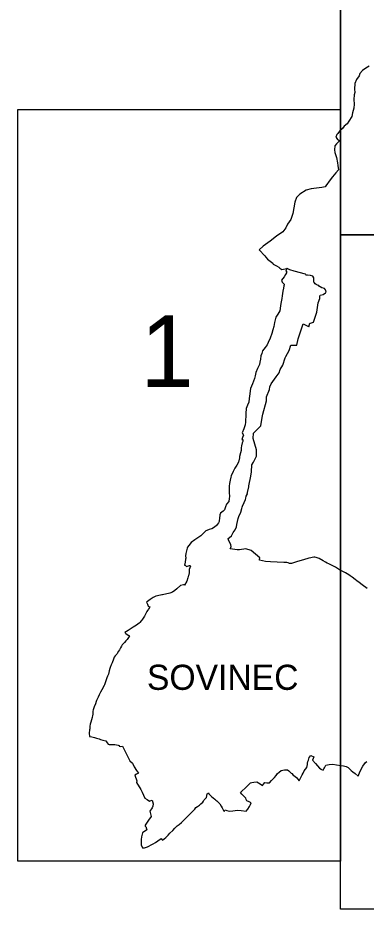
# Model space of a CAD drawing. Extents: x -547343 to -529607, y -1096298 to -1087453.
# Drawn here: x -532851 to -532756.9, y -1089566.1 to -1089325.1 of the extents above; entities that cross this region are included whole.
import ezdxf

# ---------------------------------------------------------------- set-up
doc = ezdxf.new("R2010")
doc.units = 0
doc.layers.add('Vrstva 18', color=7, linetype='Continuous')
doc.layers.add('Vrstva 9', color=7, linetype='Continuous')

msp = doc.modelspace()

# ---------------------------------------------------------------- linework, layer by layer
at = {"layer": 'Vrstva 18'}
for points in [[(-532676.65, -1089201.45), (-532763.82, -1089201.45), (-532763.82, -1089383.77), (-532676.65, -1089383.77)], [(-532763.82, -1089349.85), (-532763.82, -1089553.12), (-532850.99, -1089553.12), (-532850.99, -1089349.85)], [(-532676.65, -1089383.77), (-532676.65, -1089566.09), (-532763.82, -1089566.09), (-532763.82, -1089383.77)]]:
    msp.add_lwpolyline(points, close=True, dxfattribs=at)
for points in [[(-532756.12, -1089338.18), (-532757.02, -1089338.71), (-532757.91, -1089339.3), (-532758.64, -1089340.17), (-532758.79, -1089340.77), (-532759.5, -1089341.77), (-532759.95, -1089342.86), (-532760.04, -1089344.39), (-532759.97, -1089345.3), (-532760.18, -1089345.94), (-532760.26, -1089347.13), (-532760.16, -1089348.44), (-532760.26, -1089349.48), (-532760.58, -1089350.74), (-532760.83, -1089351.78), (-532761.57, -1089353.07), (-532762.06, -1089353.75), (-532762.86, -1089354.41), (-532763.34, -1089354.98), (-532764.01, -1089355.64), (-532764.41, -1089356.05), (-532764.57, -1089356.36), (-532764.85, -1089356.64), (-532765.1, -1089357.37), (-532764.76, -1089357.79), (-532764.12, -1089358.34), (-532764.56, -1089358.77), (-532764.96, -1089359.14), (-532765.36, -1089359.71), (-532765.44, -1089360.77), (-532765.37, -1089361.53), (-532764.92, -1089362.84), (-532764.68, -1089364.27), (-532764.6, -1089365.03), (-532764.37, -1089366.16), (-532765.12, -1089367), (-532766.04, -1089368.08), (-532766.66, -1089368.85), (-532767.86, -1089370.47), (-532768.04, -1089370.75), (-532768.93, -1089370.96), (-532771.75, -1089371.31), (-532773.16, -1089371.65), (-532774.83, -1089372.73), (-532775.76, -1089373.71), (-532776.21, -1089374.93), (-532776.74, -1089378.01), (-532777.24, -1089379.58), (-532778.15, -1089380.84), (-532778.6, -1089381.86), (-532779.45, -1089382.91), (-532781.16, -1089384.15), (-532782.81, -1089385.48), (-532784.76, -1089386.81), (-532785.82, -1089387.78), (-532784.31, -1089389.41), (-532784, -1089389.83), (-532783.56, -1089390.3), (-532782.13, -1089391.39), (-532782.02, -1089391.73), (-532781.13, -1089392.11), (-532780.53, -1089392.5), (-532780.2, -1089392.75), (-532779.69, -1089393.1), (-532778.38, -1089392.82), (-532778.63, -1089393.55), (-532778.45, -1089393.59), (-532778.48, -1089394.07), (-532778.67, -1089394.49), (-532779.07, -1089395.09), (-532779.76, -1089396.06), (-532779.58, -1089396.55), (-532779.04, -1089397.13), (-532779.08, -1089397.32), (-532779.13, -1089397.55), (-532779.26, -1089398.18), (-532779.39, -1089398.95), (-532779.61, -1089400.23), (-532779.74, -1089400.95), (-532779.92, -1089401.87), (-532780.06, -1089402.86), (-532780.17, -1089403.71), (-532780.26, -1089404.32), (-532780.8, -1089405.17), (-532781.32, -1089406.04), (-532781.64, -1089407.43), (-532781.89, -1089408.55), (-532782.13, -1089409.49), (-532782.36, -1089410.4), (-532782.88, -1089411.66), (-532783.39, -1089412.9), (-532783.67, -1089413.53), (-532784.22, -1089414.24), (-532784.93, -1089415.12), (-532785.14, -1089415.84), (-532785.33, -1089416.46), (-532785.5, -1089417.35), (-532785.65, -1089418.15), (-532785.77, -1089418.85), (-532786.25, -1089419.91), (-532786.76, -1089421.02), (-532786.92, -1089421.87), (-532787.07, -1089422.63), (-532787.61, -1089424.01), (-532788.14, -1089425.31), (-532788.41, -1089427.36), (-532788.52, -1089428.05), (-532788.65, -1089429.03), (-532788.99, -1089429.82), (-532789.37, -1089430.73), (-532789.43, -1089432.05), (-532789.46, -1089432.98), (-532789.49, -1089433.73), (-532789.55, -1089434.43), (-532789.63, -1089435.13), (-532789.99, -1089436.2), (-532790.37, -1089437.29), (-532790.05, -1089437.92), (-532790.28, -1089438.54), (-532790.5, -1089439.07), (-532790.21, -1089439.11), (-532790.24, -1089439.65), (-532790.37, -1089440.04), (-532790.63, -1089440.82), (-532790.65, -1089441.34), (-532790.67, -1089442.05), (-532790.84, -1089442.72), (-532791.09, -1089443.65), (-532791.17, -1089444.03), (-532791.4, -1089445.26), (-532791.88, -1089446.01), (-532792.39, -1089446.85), (-532792.84, -1089447.76), (-532793.39, -1089448.9), (-532793.47, -1089449.25), (-532793.68, -1089450.07), (-532793.84, -1089450.99), (-532793.89, -1089451.74), (-532793.95, -1089452.65), (-532793.9, -1089453.4), (-532793.82, -1089454.54), (-532793.89, -1089455.08), (-532794, -1089455.87), (-532794.64, -1089456.59), (-532794.87, -1089457.29), (-532795.06, -1089457.82), (-532795.21, -1089458.14), (-532795.55, -1089458.45), (-532796.29, -1089459.06), (-532796.44, -1089459.51), (-532796.46, -1089459.72), (-532796.49, -1089460.2), (-532796.65, -1089461.25), (-532796.84, -1089461.63), (-532797.08, -1089461.98), (-532797.38, -1089462.34), (-532797.92, -1089462.77), (-532798.57, -1089463.27), (-532799.28, -1089463.43), (-532799.96, -1089463.69), (-532800.18, -1089463.82), (-532800.84, -1089464.41), (-532801.6, -1089465.14), (-532802.36, -1089465.69), (-532803.21, -1089466.26), (-532804.16, -1089466.92), (-532804.81, -1089467.74), (-532805.15, -1089468.2), (-532805.27, -1089468.47), (-532805.64, -1089469.88), (-532805.69, -1089470.54), (-532805.62, -1089471.16), (-532805.67, -1089471.49), (-532805.83, -1089472.29), (-532805.94, -1089473.05), (-532805.83, -1089473.12), (-532805.54, -1089473.33), (-532805.54, -1089473.33), (-532805.52, -1089473.35), (-532805.44, -1089473.4), (-532804.66, -1089473.13), (-532804.57, -1089473.18), (-532804.45, -1089473.26), (-532804.39, -1089473.31), (-532804.36, -1089473.32), (-532804.68, -1089474.22), (-532804.74, -1089474.98), (-532804.76, -1089475.18), (-532804.94, -1089475.96), (-532804.98, -1089476.11), (-532805.08, -1089476.54), (-532805.39, -1089477.41), (-532806, -1089478.44), (-532806.09, -1089478.39), (-532806.21, -1089478.38), (-532807.02, -1089478.55), (-532807.95, -1089479.36), (-532808.05, -1089479.45), (-532808.63, -1089479.93), (-532809.2, -1089480.34), (-532809.9, -1089480.62), (-532811.93, -1089481.06), (-532812.14, -1089481.11), (-532812.42, -1089481.18), (-532813.68, -1089481.49), (-532814.05, -1089481.66), (-532814.41, -1089481.81), (-532814.68, -1089481.99), (-532815.26, -1089482.39), (-532815.58, -1089482.59), (-532815.99, -1089482.93), (-532816.21, -1089483.12), (-532816.01, -1089483.63), (-532815.75, -1089484.16), (-532815.35, -1089484.3), (-532815.44, -1089484.48), (-532815.62, -1089484.75), (-532815.74, -1089484.93), (-532815.98, -1089485.3), (-532816.11, -1089485.56), (-532816.39, -1089486.11), (-532816.58, -1089486.53), (-532816.81, -1089486.87), (-532817.13, -1089487.38), (-532817.49, -1089487.95), (-532817.66, -1089488.14), (-532818.05, -1089488.6), (-532818.25, -1089488.78), (-532818.56, -1089489), (-532818.97, -1089489.28), (-532819.37, -1089489.53), (-532819.83, -1089489.84), (-532820.42, -1089490.23), (-532821.22, -1089490.72), (-532822.09, -1089491.26), (-532822.01, -1089491.34), (-532821.81, -1089491.53), (-532821.23, -1089492.01), (-532820.81, -1089492.22), (-532821.09, -1089492.66), (-532821.44, -1089493.2), (-532821.8, -1089493.57), (-532822.21, -1089493.98), (-532822.57, -1089494.34), (-532822.78, -1089494.65), (-532823, -1089494.96), (-532823.25, -1089495.44), (-532823.54, -1089495.97), (-532823.76, -1089496.35), (-532824.16, -1089496.96), (-532824.29, -1089497.12), (-532824.69, -1089497.62), (-532824.95, -1089497.96), (-532825.17, -1089498.53), (-532825.55, -1089499.48), (-532825.79, -1089500.06), (-532826.09, -1089500.75), (-532826.16, -1089501.02), (-532826.33, -1089501.69), (-532826.55, -1089502.59), (-532826.62, -1089502.74), (-532826.75, -1089503.08), (-532826.92, -1089503.5), (-532827.14, -1089504.09), (-532827.4, -1089504.85), (-532827.6, -1089505.41), (-532827.71, -1089505.64), (-532828.3, -1089506.78), (-532828.64, -1089507.4), (-532828.86, -1089507.73), (-532829.04, -1089508.14), (-532829.31, -1089508.73), (-532829.72, -1089509.64), (-532829.83, -1089509.96), (-532830.06, -1089510.57), (-532830.34, -1089511.35), (-532830.64, -1089512.16), (-532830.7, -1089512.55), (-532830.73, -1089512.84), (-532830.78, -1089513.5), (-532830.82, -1089513.72), (-532830.96, -1089514.25), (-532831.3, -1089515.49), (-532831.48, -1089516.1), (-532831.52, -1089516.64), (-532831.58, -1089517.31), (-532831.61, -1089517.58), (-532831.69, -1089518.47), (-532831.6, -1089519.37), (-532830.97, -1089519.5), (-532830.3, -1089519.65), (-532829.75, -1089519.83), (-532829.04, -1089520.05), (-532828.64, -1089520.18), (-532828.05, -1089520.36), (-532827.21, -1089520.61), (-532827.06, -1089520.82), (-532826.83, -1089521.13), (-532826.58, -1089521.49), (-532826.37, -1089521.52), (-532825.78, -1089521.58), (-532824.83, -1089521.57), (-532823.88, -1089521.77), (-532823.65, -1089521.87), (-532823.59, -1089522.02), (-532823.38, -1089522.08), (-532822.7, -1089521.98), (-532821.22, -1089525.11), (-532820.71, -1089525.98), (-532820.03, -1089526.58), (-532819.54, -1089527.56), (-532818.97, -1089528.6), (-532818.37, -1089529.29), (-532818.74, -1089529.52), (-532818.92, -1089529.62), (-532819.38, -1089529.9), (-532818.84, -1089531.39), (-532818.98, -1089531.85), (-532817.77, -1089533.7), (-532817.44, -1089534.45), (-532816.68, -1089536.06), (-532816.07, -1089536.42), (-532815.4, -1089536.88), (-532815.23, -1089536.84), (-532814.68, -1089536.58), (-532814.43, -1089537.63), (-532814.55, -1089538.27), (-532814.68, -1089538.65), (-532815.37, -1089539.63), (-532815.02, -1089541.01), (-532815.67, -1089542.05), (-532816.64, -1089543.34), (-532816.62, -1089543.62), (-532816.37, -1089543.94), (-532816.29, -1089544.07), (-532816.22, -1089544.41), (-532816.18, -1089544.64), (-532817.28, -1089545.41), (-532817.57, -1089546.56), (-532817.65, -1089547.25), (-532817.68, -1089547.48), (-532817.68, -1089548.69), (-532817.28, -1089549.54), (-532816.82, -1089549.51), (-532815.96, -1089549.21), (-532814.6, -1089548.51), (-532814.46, -1089548.43), (-532813.78, -1089548.02), (-532813.21, -1089547.63), (-532812.28, -1089547), (-532812.06, -1089547.25), (-532811.92, -1089547.4), (-532811.06, -1089546.73), (-532810.41, -1089546.07), (-532809.91, -1089545.56), (-532809.15, -1089544.79), (-532808.58, -1089544.23), (-532807.92, -1089543.58), (-532807.42, -1089543.16), (-532806.82, -1089542.61), (-532806.38, -1089542.23), (-532805.85, -1089541.74), (-532805.4, -1089541.3), (-532804.78, -1089540.69), (-532804.23, -1089540.16), (-532803.6, -1089539.52), (-532803.21, -1089539.02), (-532802.88, -1089538.58), (-532802.46, -1089538.29), (-532801.97, -1089537.94), (-532801.56, -1089537.58), (-532801.07, -1089537.15), (-532800.89, -1089536.88), (-532800.71, -1089536.55), (-532800.51, -1089536.38), (-532800.33, -1089536.2), (-532800.02, -1089535.89), (-532799.85, -1089534.94), (-532799.64, -1089534.78), (-532799.46, -1089534.62), (-532799.41, -1089534.93), (-532799.07, -1089535.23), (-532798.92, -1089535.37), (-532798.58, -1089535.68), (-532798.23, -1089535.98), (-532797.83, -1089536.31), (-532797.51, -1089536.59), (-532797.21, -1089536.84), (-532796.87, -1089537.14), (-532796.41, -1089537.57), (-532796.07, -1089538.2), (-532795.79, -1089538.73), (-532795.45, -1089539.4), (-532795.15, -1089539.57), (-532795.01, -1089539.27), (-532794.52, -1089539.43), (-532793.96, -1089539.62), (-532792.9, -1089539.47), (-532791.71, -1089539.31), (-532790.72, -1089539.41), (-532789.32, -1089539.56), (-532788.92, -1089539.02), (-532788.43, -1089538.37), (-532788.16, -1089537.82), (-532787.94, -1089537.36), (-532788.49, -1089537.11), (-532789.15, -1089536.8), (-532789.29, -1089536.43), (-532789.4, -1089536.09), (-532789.73, -1089535.77), (-532790.48, -1089535), (-532790.89, -1089534.58), (-532790.37, -1089534.07), (-532789.62, -1089533.35), (-532789.04, -1089532.8), (-532788.14, -1089531.94), (-532787.79, -1089531.86), (-532787.23, -1089531.77), (-532786.44, -1089531.64), (-532785.58, -1089532.24), (-532784.96, -1089532.65), (-532784.63, -1089532.25), (-532784.26, -1089531.83), (-532783.74, -1089531.89), (-532783.01, -1089531.94), (-532782.45, -1089531.29), (-532781.98, -1089530.76), (-532781.67, -1089530.51), (-532781.26, -1089529.99), (-532780.84, -1089529.45), (-532780.39, -1089529.01), (-532779.92, -1089528.57), (-532779.39, -1089528.48), (-532778.97, -1089528.4), (-532778.66, -1089528.37), (-532778.19, -1089528.42), (-532777.85, -1089528.72), (-532777.47, -1089529.05), (-532777.27, -1089529.24), (-532777.16, -1089529.32), (-532776.99, -1089529.4), (-532776.61, -1089529.86), (-532776.2, -1089530.16), (-532775.63, -1089530.57), (-532775.34, -1089530.93), (-532774.99, -1089531.35), (-532774.63, -1089530.63), (-532774.21, -1089529.8), (-532773.94, -1089529.3), (-532773.63, -1089528.71), (-532773.28, -1089528.23), (-532772.93, -1089527.75), (-532772.8, -1089526.98), (-532772.74, -1089526.64), (-532772.64, -1089526.18), (-532772.52, -1089525.76), (-532772.32, -1089525.09), (-532771.88, -1089524.5), (-532771.07, -1089524.9), (-532771.38, -1089525.76), (-532770.64, -1089526.71), (-532770.07, -1089527.31), (-532769.49, -1089527.94), (-532769.1, -1089528.25), (-532768.99, -1089528.31), (-532768.5, -1089528.51), (-532768.35, -1089528.1), (-532768.21, -1089527.84), (-532767.79, -1089527.13), (-532766.87, -1089527), (-532765.94, -1089526.89), (-532764.89, -1089527.07), (-532763.76, -1089527.25), (-532763.05, -1089527.37), (-532762.32, -1089527.48), (-532761.79, -1089527.82), (-532761.51, -1089528.02), (-532761.28, -1089528.28), (-532761.01, -1089528.59), (-532760.5, -1089528.99), (-532759.91, -1089529.44), (-532759.06, -1089530.1), (-532758.68, -1089529.22), (-532758.39, -1089528.44), (-532757.8, -1089527.46), (-532757.13, -1089526.44), (-532756.76, -1089526.14)], [(-532769.45, -1089400.68), (-532769.41, -1089400.22), (-532769.39, -1089400.03), (-532768.54, -1089399.92), (-532767.95, -1089399.46), (-532767.78, -1089399.27), (-532767.71, -1089399.21), (-532767.95, -1089398.63), (-532768.22, -1089398.29), (-532768.5, -1089398.2), (-532768.86, -1089398.06), (-532769.31, -1089397.85), (-532769.5, -1089397.69), (-532769.73, -1089397.47), (-532770.06, -1089397.34), (-532770.42, -1089397.16), (-532770.73, -1089396.97), (-532770.91, -1089396.74), (-532771.04, -1089396.54), (-532771.1, -1089396.46), (-532771.1, -1089396.24), (-532771.1, -1089396.09), (-532771.08, -1089395.73), (-532771.06, -1089395.35), (-532771.31, -1089394.93), (-532771.99, -1089394.8), (-532772.76, -1089394.67), (-532773.16, -1089394.63), (-532773.18, -1089394.58), (-532773.32, -1089394.44), (-532776.36, -1089393.54), (-532777.55, -1089393.18), (-532778.06, -1089392.96), (-532778.22, -1089392.89), (-532778.38, -1089392.82)], [(-532756.69, -1089479.42), (-532758.04, -1089478.41), (-532758.77, -1089477.72), (-532759.45, -1089477.27), (-532759.92, -1089476.91), (-532760.69, -1089476.29), (-532761.21, -1089475.92), (-532761.62, -1089475.65), (-532762.02, -1089475.45), (-532762.53, -1089475.18), (-532763.78, -1089474.55), (-532764.15, -1089474.32), (-532765.24, -1089473.65), (-532765.72, -1089473.35), (-532765.96, -1089473.23), (-532766.45, -1089473), (-532767.04, -1089472.73), (-532767.42, -1089472.54), (-532767.87, -1089472.29), (-532768.58, -1089471.88), (-532769.65, -1089471.28), (-532770.45, -1089471.01), (-532770.82, -1089470.89), (-532770.95, -1089470.87), (-532771.09, -1089470.89), (-532771.47, -1089470.96), (-532771.9, -1089471.05), (-532772.41, -1089471.19), (-532773.89, -1089471.64), (-532775.49, -1089472.12), (-532776.25, -1089472.35), (-532777.1, -1089472.63), (-532777.64, -1089472.59), (-532777.97, -1089472.49), (-532778.38, -1089472.35), (-532779.16, -1089472.32), (-532780.97, -1089472.24), (-532782.79, -1089472.16), (-532784.15, -1089472.1), (-532785.71, -1089471.74), (-532785.7, -1089471.68), (-532785.69, -1089471.53), (-532785.66, -1089471.12), (-532787.94, -1089469.07), (-532789.41, -1089468.69), (-532791.16, -1089468.9), (-532791.78, -1089468.97), (-532793.66, -1089468.66), (-532793.58, -1089468.45), (-532793.5, -1089468.27), (-532793.4, -1089468.06), (-532793.5, -1089467.57), (-532794.08, -1089466.19), (-532794.22, -1089466), (-532794.26, -1089465.94), (-532793.27, -1089465.1), (-532793.02, -1089464.59), (-532792.86, -1089464.23), (-532792.29, -1089463.5), (-532791.95, -1089462.73), (-532791.82, -1089462.05), (-532791.48, -1089460.44), (-532791.28, -1089459.96), (-532790.79, -1089458.78), (-532790.46, -1089457.77), (-532790.38, -1089457.36), (-532790.3, -1089457.09), (-532789.88, -1089456.11), (-532789.52, -1089455.31), (-532789.43, -1089454.98), (-532789.29, -1089454.38), (-532789.05, -1089454.01), (-532788.98, -1089453.77), (-532789.03, -1089453.76), (-532788.99, -1089453.55), (-532788.97, -1089453.45), (-532788.65, -1089451.86), (-532788.61, -1089451.61), (-532788.1, -1089448.99), (-532787.89, -1089447.83), (-532787.79, -1089445.92), (-532787.38, -1089445.19), (-532786.5, -1089443.59), (-532786.5, -1089441.85), (-532787.43, -1089438.82), (-532787.31, -1089437.39), (-532785.35, -1089435.43), (-532785.02, -1089433.17), (-532784.87, -1089432.22), (-532783.87, -1089428.64), (-532783.82, -1089427.53), (-532783, -1089425.61), (-532782.91, -1089424.9), (-532782.6, -1089424.04), (-532781.22, -1089422.18), (-532780.38, -1089421.05), (-532780.15, -1089420.18), (-532779.45, -1089419), (-532778.83, -1089417.03), (-532778.61, -1089416.68), (-532777.75, -1089415.06), (-532777.23, -1089413.56), (-532777.11, -1089413.57), (-532775.69, -1089413.56), (-532775.25, -1089411.91), (-532773.97, -1089407.82), (-532772.54, -1089408.59), (-532772.43, -1089408.65), (-532772.15, -1089407.67), (-532771.95, -1089407.6), (-532771.14, -1089407.33), (-532770.26, -1089404.66), (-532769.85, -1089402.12), (-532769.47, -1089400.95), (-532769.45, -1089400.68)]]:
    msp.add_lwpolyline(points, dxfattribs=at)
at = {"layer": 'Vrstva 9'}
for points in [[(-532763.82, -1089201.45), (-532676.65, -1089201.45), (-532676.65, -1089383.77), (-532763.82, -1089383.77)], [(-532850.99, -1089349.85), (-532763.82, -1089349.85), (-532763.82, -1089553.12), (-532850.99, -1089553.12)], [(-532763.82, -1089383.77), (-532676.65, -1089383.77), (-532676.65, -1089566.09), (-532763.82, -1089566.09)]]:
    msp.add_lwpolyline(points, close=True, dxfattribs=at)

# ---------------------------------------------------------------- texts
at = {"layer": 'Vrstva 18'}
for s, height, p in [('1', 19.37, (-532817.91, -1089424.89)), ('SOVINEC', 6.799, (-532816.12, -1089506.79))]:
    msp.add_text(s, height=height, dxfattribs=at).set_placement(p)

doc.saveas('drawing.dxf')
